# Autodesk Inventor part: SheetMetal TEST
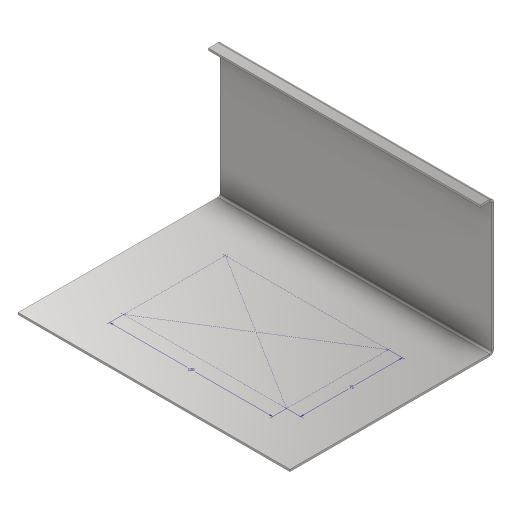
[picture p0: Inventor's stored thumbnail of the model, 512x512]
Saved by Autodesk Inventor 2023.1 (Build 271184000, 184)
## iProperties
Category: Autodesk® Inventor® Tutorial Series
Company: Fabian Stasiak CAD Consulting
Created: 2022-08
Part Number: SheetMetal TEST
Material: Steel
Document SubType Name: Sheet Metal
Designer: F.Stasiak
Density: 7.85 g/cm^3
Sheet Metal Rule: Steel 1.5 mm/Straight
Appearance: Stainless - Brushed
Catalog Web Link: www.expertbooks.eu
Thickness: 1,5
FLATAREA: =<FLAT PATTERN AREA>
Author: F.Stasiak
Subject: Sheet Metal Design. Basic and Advanced techniques
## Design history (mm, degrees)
node "Face1"
  sketch "Sketch1"
    geometry: L1 (100, -75)-(-100, -75); L2 (-100, -75)-(-100, 75); L3 (-100, 75)-(100, 75); L4 (100, 75)-(100, -75); L5 (100, -75)-(-100, 75); L6 (-100, -75)-(100, 75); 1 further point
    constraints: 12 end point, 2 midpoint, 2 parallel, 1 horizontal, 1 perpendicular
    dimensions: "d0" = 200 distance of L2.end L3.end; "d1" = 150 distance of L1.end L2.end
node "Flange1"
node "Flange2"
sketch "BASE_SKETCH"
  geometry: L1 (-60, 37.5)-(60, 37.5); L2 (60, 37.5)-(60, -37.5); L3 (60, -37.5)-(-60, -37.5); L4 (-60, -37.5)-(-60, 37.5); L5 (-60, 37.5)-(60, -37.5); L6 (60, 37.5)-(-60, -37.5); 5 further points
  constraints: 12 end point, 4 coincident, 2 midpoint, 2 parallel, 1 horizontal, 1 perpendicular
  dimensions: "d23" = 120 distance of L2.end L3.end; "d24" = 75 distance of L1.end L2.end
sketch "SIDE_SKETCH"
  geometry: L1 (24.924, 82.436)-(174.924, 82.436); L2 (174.924, 82.436)-(174.924, 22.436); L3 (174.924, 22.436)-(24.924, 22.436); L4 (24.924, 22.436)-(24.924, 82.436); 6 further points
  constraints: 8 end point, 4 coincident, 2 midpoint, 2 parallel, 1 horizontal, 1 perpendicular
  dimensions: "d25" = 150 distance of L2.end L3.end; "d26" = 60 distance of L1.end L2.end
body "Solid1"
face "Plate1" dims "d2" = 1.5 (= Thickness)
sketch "Sketch2"
  geometry: L1 through (-100, 0) direction (1, 0); L2 through (0, 50) direction (-7.89e-33, 1); L3 (0, 100)-(-200, 100); L4 (-200, 100)-(-200, 0)
  constraints: 6 end point, 1 horizontal, 1 perpendicular, 1 vertical
face "Plate2" dims "d2" = 1.5 (= Thickness), "d3" = 1.5 (= BendReliefWidth), "d4" = 0.75 (= BendReliefDepth), "d5" = 3 (= MinimumRemnant), "d6" = 1.5 (= TransitionRadius), "d7" = 100, "d8" = 90 deg, "d9" = 1.5 (= BendRadius), "d10" = 6 (= CornerReliefSize), "d11" = 1.5 (= GapSize), "d12" = 1.5 (= JacobiRadiusSize), "SeamGap" = 0.01
bend "Bend1" dims "d2" = 1.5 (= Thickness), "d3" = 1.5 (= BendReliefWidth), "d4" = 0.75 (= BendReliefDepth), "d5" = 3 (= MinimumRemnant), "d6" = 1.5 (= TransitionRadius), "d7" = 100, "d8" = 90 deg, "d9" = 1.5 (= BendRadius), "SeamGap" = 0.01
feature "Corner1" dims "d7" = 100, "d8" = 90 deg, "d10" = 6 (= CornerReliefSize), "d11" = 1.5 (= GapSize), "d12" = 1.5 (= JacobiRadiusSize)
sketch "Sketch3"
  geometry: L1 through (-100, 0) direction (1, 8.88e-17); L2 through (0, 5) direction (-1.59e-31, 1); L3 (0, 10)-(-200, 10); L4 (-200, 10)-(-200, 0)
  constraints: 6 end point, 1 horizontal, 1 perpendicular, 1 vertical
face "Plate3" dims "d2" = 1.5 (= Thickness), "d13" = 1.5 (= BendReliefWidth), "d14" = 0.75 (= BendReliefDepth), "d15" = 3 (= MinimumRemnant), "d16" = 1.5 (= TransitionRadius), "d17" = 10, "d18" = 90 deg, "d19" = 1.5 (= BendRadius), "d20" = 6 (= CornerReliefSize), "d21" = 1.5 (= GapSize), "d22" = 1.5 (= JacobiRadiusSize), "SeamGap" = 0.01
bend "Bend2" dims "d2" = 1.5 (= Thickness), "d13" = 1.5 (= BendReliefWidth), "d14" = 0.75 (= BendReliefDepth), "d15" = 3 (= MinimumRemnant), "d16" = 1.5 (= TransitionRadius), "d17" = 10, "d18" = 90 deg, "d19" = 1.5 (= BendRadius), "SeamGap" = 0.01
feature "Corner2" dims "d17" = 10, "d18" = 90 deg, "d20" = 6 (= CornerReliefSize), "d21" = 1.5 (= GapSize), "d22" = 1.5 (= JacobiRadiusSize)
other parameters: "Thickness" = 1.5 (derived), "BendRadius" = 1.5 (= Thickness), "BendReliefWidth" = 1.5 (= Thickness), "BendReliefDepth" = 0.75 (= 0.5 x Thickness), "CornerReliefSize" = 6 (= 4 x Thickness), "MinimumRemnant" = 3 (= 2 x Thickness), "TransitionRadius" = 1.5 (= BendRadius), "JacobiRadiusSize" = 1.5 (= BendRadius), "GapSize" = 1.5 (= Thickness)
